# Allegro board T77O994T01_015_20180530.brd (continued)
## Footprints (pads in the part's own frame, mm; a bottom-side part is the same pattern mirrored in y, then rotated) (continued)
GMTH134R394KO472
  round 3.404 hole 3.404 unplated: (0,0)
  round 1.016 hole 0.711: 1(3.39,1.82) 2(1.738,3.245) 3(-1.835,3.159) 4(-3.357,1.821) 5(-3.357,-1.797) 6(-1.846,-3.211) 7(1.706,-3.211) 8(3.38,-1.797)
ICT
  round 0.762 smd: 1(0,0)
ICT020
  round 0.508 smd: 1(0,0)
ICT295PAS0
  round 7.493 smd: 1(0,0)
L-S4_45X4_06-2AS0
  rect 2.159x1.651 smd: 1(0,-1.908) 2(0,1.908)
L-S5_49X5_18-2
  rect 2.819x1.905 smd: 1(0,2.296) 2(0,-2.296)
L-S5_49X5_18-2A
  rect 2.819x1.905 smd: 1(0,-2.033) 2(0,2.033)
L-S6_86X6_47-2A
  rect 3.429x2.083 smd: 1(0,-2.894) 2(0,2.894)
L-S8_3X8_1-2
  rect 3.505x2.21 smd: 1(0,-3.553) 2(0,3.553)
L-U58O293T00
  rect 0.889x0.635 smd: 1(2.36,0) 2(-2.36,0)
LD-0603S0
  rect 0.813x0.762 smd: 1(0,0.686) 2(0,-0.686)
LD-0603S0-H0_55
  rect 0.813x0.762 smd: 1(0,0.686) 2(0,-0.686)
MPTH126R295
  round 7.493 hole 3.2: 1(0,0)
MSOP-8
  rect 1.524x0.356 smd: 1(2.07,-0.975) 2(2.07,-0.325) 3(2.07,0.325) 4(2.07,0.975) 5(-2.07,0.975) 6(-2.07,0.325) 7(-2.07,-0.325) 8(-2.07,-0.975)
MSOP-8A
  rect 1.524x0.356 smd: 1(2.819,-0.975) 2(2.819,-0.325) 3(2.819,0.325) 4(2.819,0.975) 5(-2.819,0.975) 6(-2.819,0.325) 7(-2.819,-0.325) 8(-2.819,-0.975)
NUT165R276-H5_7
  round 7.01 hole 4.191: 1(0,0)
O-3_2X1_5-2A
  rect 1.905x1.016 smd: 1(0,-1.25) 2(0,1.25)
O-3_2X2_5-4GS0
  rect 1.6x1.702 smd: 1(0.95,-1.25) 2(0.95,1.25) 3(-0.95,1.25) 4(-0.95,-1.25)
O-3_2X2_5-4JS0
  rect 1.6x1.372 smd: 1(-1.197,-0.978) 2(1.197,-0.978) 3(1.197,0.978) 4(-1.197,0.978)
O-S3_2X2_5-4F
  rect 1.168x1.397 smd: 1(0.8,-1.1) 2(0.8,1.1) 3(-0.8,1.1) 4(-0.8,-1.1)
PBGA-16X16-256B-H2_2
  round 0.508 smd: A1(-7.5,-7.5) A2(-7.5,-6.5) A3(-7.5,-5.5) A4(-7.5,-4.5) A5(-7.5,-3.5) A6(-7.5,-2.5) A7(-7.5,-1.5) A8(-7.5,-0.5) A9(-7.5,0.5) A10(-7.5,1.5) A11(-7.5,2.5) A12(-7.5,3.5) A13(-7.5,4.5) A14(-7.5,5.5) A15(-7.5,6.5) A16(-7.5,7.5) B1(-6.5,-7.5) B2(-6.5,-6.5) B3(-6.5,-5.5) B4(-6.5,-4.5) B5(-6.5,-3.5) B6(-6.5,-2.5) B7(-6.5,-1.5) B8(-6.5,-0.5) B9(-6.5,0.5) B10(-6.5,1.5) B11(-6.5,2.5) B12(-6.5,3.5) B13(-6.5,4.5) B14(-6.5,5.5) B15(-6.5,6.5) B16(-6.5,7.5) C1(-5.5,-7.5) C2(-5.5,-6.5) C3(-5.5,-5.5) C4(-5.5,-4.5) C5(-5.5,-3.5) C6(-5.5,-2.5) C7(-5.5,-1.5) C8(-5.5,-0.5) C9(-5.5,0.5) C10(-5.5,1.5) C11(-5.5,2.5) C12(-5.5,3.5) C13(-5.5,4.5) C14(-5.5,5.5) C15(-5.5,6.5) C16(-5.5,7.5) D1(-4.5,-7.5) D2(-4.5,-6.5) D3(-4.5,-5.5) D4(-4.5,-4.5) D5(-4.5,-3.5) D6(-4.5,-2.5) D7(-4.5,-1.5) D8(-4.5,-0.5) D9(-4.5,0.5) D10(-4.5,1.5) D11(-4.5,2.5) D12(-4.5,3.5) D13(-4.5,4.5) D14(-4.5,5.5) D15(-4.5,6.5) D16(-4.5,7.5) E1(-3.5,-7.5) E2(-3.5,-6.5) E3(-3.5,-5.5) E4(-3.5,-4.5) E5(-3.5,-3.5) E6(-3.5,-2.5) E7(-3.5,-1.5) E8(-3.5,-0.5) E9(-3.5,0.5) E10(-3.5,1.5) E11(-3.5,2.5) E12(-3.5,3.5) E13(-3.5,4.5) E14(-3.5,5.5) E15(-3.5,6.5) E16(-3.5,7.5) F1(-2.5,-7.5) F2(-2.5,-6.5) F3(-2.5,-5.5) F4(-2.5,-4.5) F5(-2.5,-3.5) F6(-2.5,-2.5) F7(-2.5,-1.5) F8(-2.5,-0.5) F9(-2.5,0.5) F10(-2.5,1.5) F11(-2.5,2.5) F12(-2.5,3.5) F13(-2.5,4.5) F14(-2.5,5.5) F15(-2.5,6.5) F16(-2.5,7.5) G1(-1.5,-7.5) G2(-1.5,-6.5) G3(-1.5,-5.5) G4(-1.5,-4.5) G5(-1.5,-3.5) G6(-1.5,-2.5) G7(-1.5,-1.5) G8(-1.5,-0.5) G9(-1.5,0.5) G10(-1.5,1.5) G11(-1.5,2.5) G12(-1.5,3.5) G13(-1.5,4.5) G14(-1.5,5.5) G15(-1.5,6.5) G16(-1.5,7.5) H1(-0.5,-7.5) H2(-0.5,-6.5) H3(-0.5,-5.5) H4(-0.5,-4.5) H5(-0.5,-3.5) H6(-0.5,-2.5) H7(-0.5,-1.5) H8(-0.5,-0.5) H9(-0.5,0.5) H10(-0.5,1.5) H11(-0.5,2.5) H12(-0.5,3.5) H13(-0.5,4.5) H14(-0.5,5.5) H15(-0.5,6.5) H16(-0.5,7.5) J1(0.5,-7.5) J2(0.5,-6.5) J3(0.5,-5.5) J4(0.5,-4.5) J5(0.5,-3.5) J6(0.5,-2.5) J7(0.5,-1.5) J8(0.5,-0.5) J9(0.5,0.5) J10(0.5,1.5) J11(0.5,2.5) J12(0.5,3.5) J13(0.5,4.5) J14(0.5,5.5) J15(0.5,6.5) J16(0.5,7.5) K1(1.5,-7.5) K2(1.5,-6.5) K3(1.5,-5.5) K4(1.5,-4.5) K5(1.5,-3.5) K6(1.5,-2.5) K7(1.5,-1.5) K8(1.5,-0.5) K9(1.5,0.5) K10(1.5,1.5) K11(1.5,2.5) K12(1.5,3.5) K13(1.5,4.5) K14(1.5,5.5) K15(1.5,6.5) K16(1.5,7.5) L1(2.5,-7.5) L2(2.5,-6.5) L3(2.5,-5.5) L4(2.5,-4.5) L5(2.5,-3.5) L6(2.5,-2.5) L7(2.5,-1.5) L8(2.5,-0.5) L9(2.5,0.5) L10(2.5,1.5) L11(2.5,2.5) L12(2.5,3.5) L13(2.5,4.5) L14(2.5,5.5) L15(2.5,6.5) L16(2.5,7.5) M1(3.5,-7.5) M2(3.5,-6.5) M3(3.5,-5.5) M4(3.5,-4.5) M5(3.5,-3.5) M6(3.5,-2.5) M7(3.5,-1.5) M8(3.5,-0.5) M9(3.5,0.5) M10(3.5,1.5) M11(3.5,2.5) M12(3.5,3.5) M13(3.5,4.5) M14(3.5,5.5) M15(3.5,6.5) M16(3.5,7.5) N1(4.5,-7.5) N2(4.5,-6.5) N3(4.5,-5.5) N4(4.5,-4.5) N5(4.5,-3.5) N6(4.5,-2.5) N7(4.5,-1.5) N8(4.5,-0.5) N9(4.5,0.5) N10(4.5,1.5) N11(4.5,2.5) N12(4.5,3.5) N13(4.5,4.5) N14(4.5,5.5) N15(4.5,6.5) N16(4.5,7.5) P1(5.5,-7.5) P2(5.5,-6.5) P3(5.5,-5.5) P4(5.5,-4.5) P5(5.5,-3.5) P6(5.5,-2.5) P7(5.5,-1.5) P8(5.5,-0.5) P9(5.5,0.5) P10(5.5,1.5) P11(5.5,2.5) P12(5.5,3.5) P13(5.5,4.5) P14(5.5,5.5) P15(5.5,6.5) P16(5.5,7.5) R1(6.5,-7.5) R2(6.5,-6.5) R3(6.5,-5.5) R4(6.5,-4.5) R5(6.5,-3.5) R6(6.5,-2.5) R7(6.5,-1.5) R8(6.5,-0.5) R9(6.5,0.5) R10(6.5,1.5) R11(6.5,2.5) R12(6.5,3.5) R13(6.5,4.5) R14(6.5,5.5) R15(6.5,6.5) R16(6.5,7.5) T1(7.5,-7.5) T2(7.5,-6.5) T3(7.5,-5.5) T4(7.5,-4.5) T5(7.5,-3.5) T6(7.5,-2.5) T7(7.5,-1.5) T8(7.5,-0.5) T9(7.5,0.5) T10(7.5,1.5) T11(7.5,2.5) T12(7.5,3.5) T13(7.5,4.5) T14(7.5,5.5) T15(7.5,6.5) T16(7.5,7.5)
R-0402H016HS40
  custom 0.114x0.114 smd: 1(0,-0.381) 2(0,0.381)
R-0402S0
  custom 0.127x0.127 smd: 1(0,-0.406) 2(0,0.406)
R-0603-TESTS1
  custom 0.191x0.191 smd: 1(0,-0.686)
  custom 0.229x0.229 smd: 2(0,0.686)
R-0603S0
  custom 0.191x0.191 smd: 1(0,-0.686) 2(0,0.686)
R-0805
  custom 0.254x0.254 smd: 1(0,-0.889) 2(0,0.889)
R-1206
  custom 0.362x0.362 smd: 1(0,-1.333) 2(0,1.333)
R-1210
  custom 0.381x0.381 smd: 1(0,-1.27) 2(0,1.27)
R-2010
  custom 0.464x0.464 smd: 1(0,-2.121) 2(0,2.121)
R-S3_1X1_6-2
  custom 0.362x0.362 smd: 1(0,-1.333) 2(0,1.333)
S-UQFN-4X4-32BSH
  custom 0.064x0.064 smd: 1(-1.4,-1.956) 8(1.4,-1.956) 9(1.956,-1.4) 16(1.956,1.4) 17(1.4,1.956) 24(-1.4,1.956) 25(-1.956,1.4) 32(-1.956,-1.4)
  rect 0.254x0.813 smd: 2(-1,-1.956) 3(-0.6,-1.956) 4(-0.2,-1.956) 5(0.2,-1.956) 6(0.6,-1.956) 7(1,-1.956) 18(1,1.956) 19(0.6,1.956) 20(0.2,1.956) 21(-0.2,1.956) 22(-0.6,1.956) 23(-1,1.956)
  rect 0.813x0.254 smd: 10(1.956,-1) 11(1.956,-0.6) 12(1.956,-0.2) 13(1.956,0.2) 14(1.956,0.6) 15(1.956,1) 26(-1.956,1) 27(-1.956,0.6) 28(-1.956,0.2) 29(-1.956,-0.2) 30(-1.956,-0.6) 31(-1.956,-1)
  rect 2.794x2.794 smd: 33(0,0)
SC-70-5A
  rect 0.914x0.356 smd: 1(1.003,-0.65) 2(1.003,0) 3(1.003,0.65) 4(-1.003,0.65) 5(-1.003,-0.65)
SO-8G
  rect 1.651x0.635 smd: 1(3.52,-1.905) 2(3.52,-0.635) 3(3.52,0.635) 4(3.52,1.905) 5(-3.52,1.905) 6(-3.52,0.635) 7(-3.52,-0.635) 8(-3.52,-1.905)
SO-8GSHS0
  rect 1.651x0.635 smd: 1(2.555,-1.905) 2(2.555,-0.635) 3(2.555,0.635) 4(2.555,1.905) 5(-2.555,1.905) 6(-2.555,0.635) 7(-2.555,-0.635) 8(-2.555,-1.905)
  rect 2.388x3.2 smd: 9(0,0)
SO-8H1_75
  rect 1.651x0.635 smd: 1(2.555,-1.905) 2(2.555,-0.635) 3(2.555,0.635) 4(2.555,1.905) 5(-2.555,1.905) 6(-2.555,0.635) 7(-2.555,-0.635) 8(-2.555,-1.905)
SOT-23-6
  rect 1.067x0.559 smd: 1(1.359,-0.95) 2(1.359,0) 3(1.359,0.95) 4(-1.359,0.95) 5(-1.359,0) 6(-1.359,-0.95)
SOT-23-8A
  rect 1.194x0.406 smd: 1(1.3,-0.975) 2(1.3,-0.325) 3(1.3,0.325) 4(1.3,0.975) 5(-1.3,0.975) 6(-1.3,0.325) 7(-1.3,-0.325) 8(-1.3,-0.975)
SOT-23BH1_11
  rect 1.067x1.016 smd: 1(0.92,-0.951) 2(0.92,0.951) 3(-0.921,0)
SOT-353-H1_1S0
  rect 0.914x0.356 smd: 1(1.003,-0.65) 2(1.003,0) 3(1.003,0.65) 4(-1.003,0.65) 5(-1.003,-0.65)
SOT-363S0
  rect 0.914x0.356 smd: 1(1.003,-0.65) 2(1.003,0) 3(1.003,0.65) 4(-1.003,0.65) 5(-1.003,0) 6(-1.003,-0.65)
SSOP-16C
  rect 1.524x0.356 smd: 1(2.819,-2.275) 2(2.819,-1.625) 3(2.819,-0.975) 4(2.819,-0.325) 5(2.819,0.325) 6(2.819,0.975) 7(2.819,1.625) 8(2.819,2.275) 9(-2.819,2.275) 10(-2.819,1.625) 11(-2.819,0.975) 12(-2.819,0.325) 13(-2.819,-0.325) 14(-2.819,-0.975) 15(-2.819,-1.625) 16(-2.819,-2.275)
SSOP-20
  rect 1.524x0.356 smd: 1(2.819,-2.925) 2(2.819,-2.275) 3(2.819,-1.625) 4(2.819,-0.975) 5(2.819,-0.325) 6(2.819,0.325) 7(2.819,0.975) 8(2.819,1.625) 9(2.819,2.275) 10(2.819,2.925) 11(-2.819,2.925) 12(-2.819,2.275) 13(-2.819,1.625) 14(-2.819,0.975) 15(-2.819,0.325) 16(-2.819,-0.325) 17(-2.819,-0.975) 18(-2.819,-1.625) 19(-2.819,-2.275) 20(-2.819,-2.925)
SSOP-24C
  rect 1.524x0.356 smd: 1(2.819,-3.575) 2(2.819,-2.925) 3(2.819,-2.275) 4(2.819,-1.625) 5(2.819,-0.975) 6(2.819,-0.325) 7(2.819,0.325) 8(2.819,0.975) 9(2.819,1.625) 10(2.819,2.275) 11(2.819,2.925) 12(2.819,3.575) 13(-2.819,3.575) 14(-2.819,2.925) 15(-2.819,2.275) 16(-2.819,1.625) 17(-2.819,0.975) 18(-2.819,0.325) 19(-2.819,-0.325) 20(-2.819,-0.975) 21(-2.819,-1.625) 22(-2.819,-2.275) 23(-2.819,-2.925) 24(-2.819,-3.575)
TLGA-3X3-12SH
  rect 0.635x0.381 smd: 1(1.467,-1.25) 2(1.467,-0.75) 3(1.467,-0.25) 4(1.467,0.25) 5(1.467,0.75) 6(1.467,1.25) 7(-1.467,1.25) 8(-1.467,0.75) 9(-1.467,0.25) 10(-1.467,-0.25) 11(-1.467,-0.75) 12(-1.467,-1.25)
  rect 2.057x2.794 smd: 13(0,0)
TQFN-2X2-8FSHS0
  rect 0.483x0.381 smd: 1(0.911,-0.75) 2(0.911,-0.25) 3(0.911,0.25) 4(0.911,0.75) 5(-0.911,0.75) 6(-0.911,0.25)
  rect 0.203x0.203 smd: 7(-0.898,-0.252) 8(-0.893,-0.748)
  rect 0.991x1.702 smd: 9(0,0)
TQFN-3X3-10FSHS1
  rect 0.813x0.381 smd: 1(1.455,-1) 2(1.455,-0.5) 3(1.455,0) 4(1.455,0.5) 5(1.455,1) 6(-1.455,1) 7(-1.455,0.5) 8(-1.455,0) 9(-1.455,-0.5) 10(-1.455,-1)
  rect 1.727x2.565 smd: 11(0,0)
TQFN-3X3-10GSH
  rect 0.813x0.381 smd: 1(1.455,-1) 2(1.455,-0.5) 3(1.455,0) 4(1.455,0.5) 5(1.455,1) 6(-1.455,1) 7(-1.455,0.5) 8(-1.455,0) 9(-1.455,-0.5) 10(-1.455,-1)
  custom 0.423x0.423 smd: 11(0,0)
TQFN-3X3-16TSHS0
  custom 0.095x0.095 smd: 1(-0.75,-1.457) 4(0.75,-1.457) 5(1.457,-0.75) 8(1.457,0.75) 9(0.75,1.457) 12(-0.75,1.457) 13(-1.457,0.75) 16(-1.457,-0.75)
  rect 0.381x0.813 smd: 2(-0.25,-1.457) 3(0.25,-1.457) 10(0.25,1.457) 11(-0.25,1.457)
  rect 0.813x0.381 smd: 6(1.457,-0.25) 7(1.457,0.25) 14(-1.457,0.25) 15(-1.457,-0.25)
  rect 1.803x1.803 smd: 17(0,0)
TQFN-5X5-32NSH
  rect 0.381x0.813 smd: 1(-1.75,-2.456) 2(-1.25,-2.456) 3(-0.75,-2.456) 4(-0.25,-2.456) 5(0.25,-2.456) 6(0.75,-2.456) 7(1.25,-2.456) 8(1.751,-2.456) 17(1.751,2.456) 18(1.25,2.456) 19(0.75,2.456) 20(0.25,2.456) 21(-0.25,2.456) 22(-0.75,2.456) 23(-1.25,2.456) 24(-1.75,2.456)
  rect 0.813x0.381 smd: 9(2.455,-1.75) 10(2.455,-1.25) 11(2.455,-0.75) 12(2.455,-0.25) 13(2.455,0.25) 14(2.455,0.75) 15(2.455,1.25) 16(2.455,1.751) 25(-2.455,1.751) 26(-2.455,1.25) 27(-2.455,0.75) 28(-2.455,0.25) 29(-2.455,-0.25) 30(-2.455,-0.75) 31(-2.455,-1.25) 32(-2.455,-1.75)
  rect 3.708x3.708 smd: 33(0,0)
TQFN-6X5-22SHS1
  rect 0.914x0.381 smd: 1(2.406,-2.501) 2(2.406,-2.001) 3(2.406,-1.5) 4(2.406,-1) 5(2.406,-0.5) 8(-2.406,-0.5) 9(-2.406,-1) 10(-2.406,-1.5) 11(-2.406,-2.001) 12(-2.406,-2.501)
  rect 0.305x0.305 smd: 6(2.406,1) 7(-2.406,1)
  custom 0.85x0.85 smd: 13(0,0)
TSSOP-8S2
  rect 1.092x0.305 smd: 1(1.511,-0.75) 2(1.511,-0.25) 3(1.511,0.25) 4(1.511,0.75) 5(-1.511,0.75) 6(-1.511,0.25) 7(-1.511,-0.25) 8(-1.511,-0.75)
ULGA-1_8X1_2-8
  rect 0.864x0.297 smd: 1(0.483,-0.6) 2(0.483,-0.2) 3(0.483,0.2) 4(0.483,0.6) 5(-0.483,0.6) 6(-0.483,0.2) 7(-0.483,-0.2) 8(-0.483,-0.6)
UM-6BH1_1
  rect 0.914x0.356 smd: 1(1.003,-0.65) 2(1.003,0) 3(1.003,0.65) 4(-1.003,0.65) 5(-1.003,0) 6(-1.003,-0.65)
unnamed
  round 1.016 smd: (0,0)

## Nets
GND: BAT1.P2(CATHODE) C17.2 C18.2 C19.1 C20.1 C21.1 C22.2 C23.2 C24.1 C25.1 C26.2 C27.2 C28.2 C29.2 C30.2 C31.2 C32.2 C33.2 C34.2 C35.2 C36.2 C37.2 C38.2 C39.2 C40.2 C41.2 C42.2 C43.2 C44.2 C45.2 C46.2 C47.2 C48.2 C49.2 C50.2 C51.2 C52.2 C53.2 C54.2 C55.2 C56.2 C57.2 C58.2 C59.2 C60.2 C61.2 C62.2 C63.2 C64.2 C65.2 C66.2 C67.2 C68.2 C69.2 C70.2 C71.2 C72.2 C73.2 C74.2 C75.2 C76.2 C77.2 C78.2 C79.2 C80.2 C81.2 C82.2 C83.2 C84.2 C85.2 C86.2 C87.2 C88.2 C89.2 C90.2 C91.2 C92.2 C93.2 C94.2 C95.2 C96.2 C97.2 C98.2 C99.2 C100.2 C101.2 C102.2 C103.2 C104.2 C107.2 C108.2 C114.2 C116.2 C117.2 C118.2 C119.2 C120.2 C121.2 C122.2 C123.2 C124.2 C125.2 C126.2 C127.2 C128.2 C129.2 C130.2 C131.2 C132.2 C133.2 C134.2 C135.2 C136.2 C137.2 C138.2 C139.2 C140.2 C141.2 C144.2 C145.2 C146.2 C147.2 C148.2 C151.2 C152.2 C153.2 C154.2 C155.2 C156.2 C157.2 C158.2 C159.2 C160.2 C161.2 C162.2 C163.2 C164.2 C165.2 C166.2 C167.2 C168.2 C169.2 C170.2 C171.2 C172.2 C173.2 C174.2 C175.2 C176.2 C177.2 C178.2 C179.2 C180.2 C181.2 C182.2 C183.2 C185.2 C186.2 C187.2 C188.2 C189.2 C190.2 C191.2 C192.2 C193.2 C198.2 C199.2 C200.2 C205.2 C206.2 C207.2 C208.2 C209.2 C210.2 C3812.2 C3813.2 CN1.1(VSS_0) CN1.2(VSS_21) CN1.5(VSS_1) CN1.6(VSS_22) CN1.9(VSS_2) CN1.10(VSS_23) CN1.12(DM0_L_DBI0_L) CN1.14(VSS_24) CN1.15(VSS_3) CN1.18(VSS_25) CN1.19(VSS_4) CN1.22(VSS_26) CN1.23(VSS_5) CN1.26(VSS_27) CN1.27(VSS_6) CN1.30(VSS_28) CN1.31(VSS_7) CN1.33(DM1_L_DBI1_L) CN1.35(VSS_8) CN1.36(VSS_29) CN1.39(VSS_9) CN1.40(VSS_30) CN1.43(VSS_10) CN1.44(VSS_31) CN1.47(VSS_11) CN1.48(VSS_32) CN1.51(VSS_12) CN1.52(VSS_33) CN1.54(DM2_L_DBI2_L) CN1.56(VSS_34) CN1.57(VSS_13) CN1.60(VSS_35) CN1.61(VSS_14) CN1.64(VSS_36) CN1.65(VSS_15) CN1.68(VSS_37) CN1.69(VSS_16) CN1.72(VSS_38) CN1.73(VSS_17) CN1.75(DM3_L_DBI3_L) CN1.77(VSS_18) CN1.78(VSS_39) CN1.81(VSS_19) CN1.82(VSS_40) CN1.85(VSS_20) CN1.86(VSS_41) CN1.89(VSS_42) CN1.90(VSS_49) CN1.93(VSS_43) CN1.94(VSS_50) CN1.96(DBI8_L) CN1.98(VSS_51) CN1.99(VSS_44) CN1.102(VSS_52) CN1.103(VSS_45) CN1.106(VSS_53) CN1.107(VSS_46) CN1.167(VSS_47) CN1.168(VSS_54) CN1.171(VSS_48) CN1.172(VSS_55) CN1.175(VSS_56) CN1.176(VSS_75) CN1.178(DM4_L_DBI4_L) CN1.180(VSS_76) CN1.181(VSS_57) CN1.184(VSS_77) CN1.185(VSS_58) CN1.188(VSS_78) CN1.189(VSS_59) CN1.192(VSS_79) CN1.193(VSS_60) CN1.196(VSS_80) CN1.197(VSS_61) CN1.199(DM5_L_DBI5_L) CN1.201(VSS_62) CN1.202(VSS_81) CN1.205(VSS_63) CN1.206(VSS_82) CN1.209(VSS_64) CN1.210(VSS_83) CN1.213(VSS_65) CN1.214(VSS_84) CN1.217(VSS_66) CN1.218(VSS_85) CN1.220(DM6_L_DBI6_L) CN1.222(VSS_86) CN1.223(VSS_67) CN1.226(VSS_87) CN1.227(VSS_68) CN1.230(VSS_88) CN1.231(VSS_69) CN1.234(VSS_89) CN1.235(VSS_70) CN1.238(VSS_90) CN1.239(VSS_71) CN1.241(DM7_L_DBI7_L) CN1.243(VSS_72) CN1.244(VSS_91) CN1.247(VSS_73) CN1.248(VSS_92) CN1.251(VSS_74) CN1.252(VSS_93) CN1.S1 CN1.S2 CN2.1(VSS_0) CN2.2(VSS_21) CN2.5(VSS_1) CN2.6(VSS_22) CN2.9(VSS_2) CN2.10(VSS_23) CN2.12(DM0_L_DBI0_L) CN2.14(VSS_24) CN2.15(VSS_3) CN2.18(VSS_25) CN2.19(VSS_4) CN2.22(VSS_26) CN2.23(VSS_5) CN2.26(VSS_27) CN2.27(VSS_6) CN2.30(VSS_28) CN2.31(VSS_7) CN2.33(DM1_L_DBI1_L) CN2.35(VSS_8) CN2.36(VSS_29) CN2.39(VSS_9) CN2.40(VSS_30) CN2.43(VSS_10) CN2.44(VSS_31) CN2.47(VSS_11) CN2.48(VSS_32) CN2.51(VSS_12) CN2.52(VSS_33) CN2.54(DM2_L_DBI2_L) CN2.56(VSS_34) CN2.57(VSS_13) CN2.60(VSS_35) CN2.61(VSS_14) CN2.64(VSS_36) CN2.65(VSS_15) CN2.68(VSS_37) CN2.69(VSS_16) CN2.72(VSS_38) CN2.73(VSS_17) CN2.75(DM3_L_DBI3_L) CN2.77(VSS_18) CN2.78(VSS_39) CN2.81(VSS_19) CN2.82(VSS_40) CN2.85(VSS_20) CN2.86(VSS_41) CN2.89(VSS_42) CN2.90(VSS_49) CN2.93(VSS_43) CN2.94(VSS_50) CN2.96(DBI8_L) CN2.98(VSS_51) CN2.99(VSS_44) CN2.102(VSS_52) CN2.103(VSS_45) CN2.106(VSS_53) CN2.107(VSS_46) CN2.167(VSS_47) CN2.168(VSS_54) CN2.171(VSS_48) CN2.172(VSS_55) CN2.175(VSS_56) CN2.176(VSS_75) CN2.178(DM4_L_DBI4_L) CN2.180(VSS_76) CN2.181(VSS_57) CN2.184(VSS_77) CN2.185(VSS_58) CN2.188(VSS_78) CN2.189(VSS_59) CN2.192(VSS_79) CN2.193(VSS_60) CN2.196(VSS_80) CN2.197(VSS_61) CN2.199(DM5_L_DBI5_L) CN2.201(VSS_62) CN2.202(VSS_81) CN2.205(VSS_63) CN2.206(VSS_82) CN2.209(VSS_64) CN2.210(VSS_83) CN2.213(VSS_65) CN2.214(VSS_84) CN2.217(VSS_66) CN2.218(VSS_85) CN2.220(DM6_L_DBI6_L) CN2.222(VSS_86) CN2.223(VSS_67) CN2.226(VSS_87) CN2.227(VSS_68) CN2.230(VSS_88) CN2.231(VSS_69) CN2.234(VSS_89) CN2.235(VSS_70) CN2.238(VSS_90) CN2.239(VSS_71) CN2.241(DM7_L_DBI7_L) CN2.243(VSS_72) CN2.244(VSS_91) CN2.247(VSS_73) CN2.248(VSS_92) CN2.251(VSS_74) CN2.252(VSS_93) CN2.S1 CN2.S2 J1.2 J2.4 J6.2 J8.2 J8.10 J9.3(GND_3) J9.9(GND_9) J9.15(GND_15) J9.27(GND_27) J9.33(GND_33) J9.39(GND_39) J9.45(GND_45) J9.51(GND_51) J9.57(GND_57) J9.71(GND_71) J9.73(GND_73) J9.S1 J9.S2 J10.A4(GND_1) J10.A12(GND_2) J10.A15(GND_3) J10.A18(GND_4) J10.A20(GND_5) J10.A23(GND_6) J10.A24(GND_7) J10.A27(GND_8) J10.A28(GND_9) J10.A31(GND_10) J10.A34(GND_11) J10.A37(GND_12) J10.A38(GND_13) J10.A41(GND_14) J10.A42(GND_15) J10.A45(GND_16) J10.A46(GND_17) J10.A49(GND_18) J10.A51(GND_19) J10.A54(GND_20) J10.A55(GND_21) J10.A58(GND_22) J10.A59(GND_23) J10.A62(GND_24) J10.A63(GND_25) J10.A66(GND_26) J10.A67(GND_27) J10.A70(GND_28) J10.A71(GND_29) J10.A74(GND_30) J10.A75(GND_31) J10.A78(GND_32) J10.A79(GND_33) J10.A82(GND_34) J10.B4(GND_35) J10.B7(GND_36) J10.B13(GND_37) J10.B16(GND_38) J10.B18(GND_39) J10.B21(GND_40) J10.B22(GND_41) J10.B25(GND_42) J10.B26(GND_43) J10.B29(GND_44) J10.B32(GND_45) J10.B35(GND_46) J10.B36(GND_47) J10.B39(GND_48) J10.B40(GND_49) J10.B43(GND_50) J10.B44(GND_51) J10.B47(GND_52) J10.B49(GND_53) J10.B52(GND_54) J10.B53(GND_55) J10.B56(GND_56) J10.B57(GND_57) J10.B60(GND_58) J10.B61(GND_59) J10.B64(GND_60) J10.B65(GND_61) J10.B68(GND_62) J10.B69(GND_63) J10.B72(GND_64) J10.B73(GND_65) J10.B76(GND_66) J10.B77(GND_67) J10.B80(GND_68) J11.1 J11.2 J12.1 J12.2 J12.7 J12.8 J12.13 J12.14 J12.19 J12.20 J12.25 J12.26 J12.31 J12.32 J12.37 J12.38 J12.49 J12.50 J12.59 M1.1(GND1) M1.2(GND2) M1.3(GND3) M1.4(GND4) M1.5(GND5) M1.6(GND6) M1.7(GND7) M1.8(GND8) M2.1(GND1) M2.2(GND2) M2.3(GND3) M2.4(GND4) M2.5(GND5) M2.6(GND6) M2.7(GND7) M2.8(GND8) M3.1(GND1) M3.2(GND2) M3.3(GND3) M3.4(GND4) M3.5(GND5) M3.6(GND6) M3.7(GND7) M3.8(GND8) M4.1(GND1) M4.2(GND2) M4.3(GND3) M4.4(GND4) M4.5(GND5) M4.6(GND6) M4.7(GND7) M4.8(GND8) MHS1.1 MHS2.1 MHS3.1 MHS4.1 PC1.2 PC3.2 PC6.2 PC7.2 PC8.2 PC9.2 PC10.2 PC11.2 PC12.2 PC13.2 PC15.2 PC16.2 PC17.2 PC20.2 PC22.2 PC23.2 PC24.2 PC25.2 PC26.2 PC27.2 PC28.2 PC29.2 PC30.2 PC31.2 PC32.2 PC33.2 PC34.2 PC35.2 PC36.2 PC37.2 PC38.2 PC39.2 PC40.2 PC41.2 PC44.2 PC45.2 PC46.2 PC47.2 PC48.2 PC52.2 PC67.2 PC68.2 PC69.2 PC70.2 PC71.2 PC72.2 PC75.2 PC77.2 PC78.2 PC79.2 PC80.2 PC81.2 PC82.2 PC83.2 PC84.2 PC111.2 PC112.2 PC114.2 PC115.2 PC139.2 PC140.2 PC142.2 PC144.2 PC146.2 PC147.2 PC148.2 PC151.2 PC152.2(C) PC162.2 PC163.2 PC166.2 PC170.2 PC171.2 PC172.2 PC173.2(C) PC174.2 PC175.2 PC176.2 PC179.2(C) PC180.2 PC182.2 PC183.2 PC184.2 PC185.2(C) PC194.2 PC195.2 PC196.2 PC199.2 PC200.2 PC201.2 PC202.2 PC203.2 PC204.2 PC205.2 PC206.2 PC208.2 PC209.2 PC211.2 PC212.2 PC213.2 PC216.2 PC217.2 PC218.2 PC219.2 PC220.2 PC222.2 PC223.2 PC224.2 PC225.2 PC226.2 PC227.2 PC228.2 PC229.2 PC230.2 PC231.2 PC232.2(C) PC237.2(C) PC242.2(C) PC243.2 PC244.2 PC246.2 PC247.2 PC248.2 PC249.2 PC250.2 PC252.2 PC255.2 PC256.2(C) PC257.2 PC258.2 PC259.2 PC262.2 PC263.2 PC264.2 PC265.2 PC266.2 PC267.2 PC270.2 PC271.2 PC272.2 PC273.2 PC274.2 PC275.2 PC284.2(C) PC292.2(C) PC293.2(C) PC295.2 PC296.2 PC297.2 PC298.2 PC299.2 PC300.2 PC301.2 PC302.2 PC303.2 PC304.2 PC305.2 PC306.2 PC307.2 PC309.2 PC316.2 PC318.2 PC322.2 PC323.2(C) PC324.2(C) PC325.2 PC326.2 PC327.2 PC330.2 PC331.2 PC336.2 PC340.2 PC349.2 PJ20.2 PJ21.2 PJ22.2 PR1.2 PR2.2 PR12.2 PR14.2 PR17.2 PR19.2 PR20.2 PR24.2 PR25.2 PR32.2 PR34.2 PR37.2 PR116.2 PR123.2 PR136.2 PR160.2 PR187.2 PR192.1 PR192.2 PR207.2 PR215.1 PR217.2 PR222.2 PR223.2 PR226.2 PR228.2 PR231.2 PR233.2 PR235.2 PR237.2 PR239.2 PR246.2 PR259.2 PR260.2 PR265.2 PR278.2 PR304.2 PU1.1(GND) PU2.5(GND) PU2.9(PAD) PU5.6(GND) PU5.11(E-PAD) PU6.6(GND) PU6.11(E-PAD) PU11.4(PGND) PU11.8(GND) PU11.11(E-PAD) PU14.3(GND1) PU14.4(GND2) PU14.5(AGND) PU14.17(POWER PAD) PU18.13(PGND) PU19.13(PGND) PU20.1(GND) PU22.13(PGND) PU24.4(GND) PU25.4(GND) PU26.13(PGND) Q1.1(S1) Q1.4(S2) Q2.2(E) Q3.2(E) Q4.1(S1) Q4.4(S2) Q5.1(S1) Q5.4(S2) Q6.2(E) R2.1 R3.1 R16.1 R17.2 R32.2 R37.1 R38.1 R84.1 R87.1 R90.1 R93.1 R95.1 R96.2 R97.1 R100.2 R123.1 R124.1 R131.1 R132.1 R135.1 R137.1 R138.1 R140.1 R141.1 R142.1 R143.1 R144.1 R145.1 R147.1 R149.2 R166.2 R167.2 R168.2 R169.1 R170.1 R171.1 R172.1 R173.1 R176.1 R178.2 R179.2 R185.2 R191.2 R203.2 R212.2 R222.2 R224.2 R226.2 R232.2 R233.2 R234.2 R238.2 R239.2 R244.2 R245.2 R246.2 R247.2 R253.1 R254.2 R255.2 R256.2 R257.2 R263.2 R264.2 R265.2 R266.2 R267.2 R274.2 R275.2 R276.2 R277.2 R282.2 R283.2 R284.2 R285.2 R286.2 R292.2 R293.2 R294.2 R295.2 R300.2 R301.2 R302.2 R303.2 R319.2 R320.2 R321.2 R336.2 R337.2 R350.1 R352.1 R362.2 R369.2 R387.2 R423.2 R425.2 R427.2 R429.2 R431.2 R433.2 R435.2 R446.2 R448.1 R449.2 R460.1 U1.A3(VSS1) U1.A5(VSS3) U1.A6(VSS4) U1.A20(VSS0) U1.A77(VSS6) U1.AA12(VSS2) U1.AA14(VSS533) U1.AA16(VSS534) U1.AA19(VSS530) U1.AA21(VSS18) U1.AA23(VSS7) U1.AA25(VSS8) U1.AA56(VSS11) U1.AA60(VSS12) U1.AA62(VSS13) U1.AA69(VSS14) U1.AB5(VSS15) U1.AB74(VSS16) U1.AC2(VSS21) U1.AC12(VSS17) U1.AC16(VSS19) U1.AC18(VSS20) U1.AC27(VSS22) U1.AC58(VSS24) U1.AD5(VSS26) U1.AE7(VSS32) U1.AE11(VSS27) U1.AE14(VSS23) U1.AE19(VSS28) U1.AE23(VSS29) U1.AE64(VSS30) U1.AE67(VSS31) U1.AE71(VSS33) U1.AF5(VSS34) U1.AF9(VSS38) U1.AF74(VSS35) U1.AF76(VSS36) U1.AF78(VSS37) U1.AG12(VSS41) U1.AG16(VSS52) U1.AG21(VSS542) U1.AG62(VSS39) U1.AH3(VSS48) U1.AH5(VSS50) U1.AH12(VSS40) U1.AH16(VSS42) U1.AH18(VSS43) U1.AH19(VSS44) U1.AH25(VSS45) U1.AH27(VSS46) U1.AH28(VSS47) U1.AH30(VSS49) U1.AH53(VSS51) U1.AH56(VSS53) U1.AH66(VSS54) U1.AH69(VSS55) U1.AH74(VSS56) U1.AK12(VSS543) U1.AK16(VSS57) U1.AK19(VSS58) U1.AK60(VSS61) U1.AK75(VSS62) U1.AK77(VSS63) U1.AL7(VSS67) U1.AL11(VSS64) U1.AL64(VSS65) U1.AL67(VSS66) U1.AL71(VSS68) U1.AM9(VSS73) U1.AM19(VSS69) U1.AM21(VSS70) U1.AM28(VSS71) U1.AM30(VSS72) U1.AN5(VSS74) U1.AN74(VSS75) U1.AN76(VSS76) U1.AP14(VSS77) U1.AP19(VSS78) U1.AP23(VSS79) U1.AP53(VSS59) U1.AR1(VSS82) U1.AR3(VSS86) U1.AR5(VSS87) U1.AR12(VSS83) U1.AR19(VSS84) U1.AR25(VSS85) U1.AR53(VSS60) U1.AR55(VSS88) U1.AR56(VSS80) U1.AR60(VSS89) U1.AU1(VSS92) U1.AU3(VSS97) U1.AU5(VSS99) U1.AU19(VSS93) U1.AU23(VSS94) U1.AU25(VSS95) U1.AU28(VSS96) U1.AU30(VSS98) U1.AU53(VSS123) U1.AU55(VSS100) U1.AU56(VSS101) U1.AU58(VSS102) U1.AU62(VSS103) U1.AU66(VSS104) U1.AU69(VSS105) U1.AU72(VSS106) U1.AU74(VSS107) U1.AU76(VSS91) U1.AU78(VSS90) U1.AV2(VSS190) U1.AV64(VSS108) U1.AV67(VSS109) U1.AV71(VSS110) U1.AV75(VSS111) U1.AV77(VSS112) U1.AW5(VSS113) U1.AW9(VSS114) U1.B2(VSS115) U1.B3(VSS531) U1.B48(VSS191) U1.B61(VSS416) U1.B74(VSS10) U1.B76(VSS436) U1.B77(VSS117) U1.B78(VSS118) U1.BA3(VSS122) U1.BA12(VSS119) U1.BA16(VSS120) U1.BA28(VSS121) U1.BA56(VSS124) U1.BB2(VSS203) U1.BB19(VSS125) U1.BB33(VSS255) U1.BB35(VSS126) U1.BD1(VSS127) U1.BD5(VSS130) U1.BD14(VSS128) U1.BD33(VSS129) U1.BE9(VSS138) U1.BE28(VSS131) U1.BE35(VSS132) U1.BE66(VSS133) U1.BE69(VSS134) U1.BE72(VSS135) U1.BE75(VSS136) U1.BE77(VSS137) U1.BF5(VSS141) U1.BF26(VSS139) U1.BF30(VSS140) U1.BF56(VSS142) U1.BF64(VSS143) U1.BF67(VSS144) U1.BF71(VSS145) U1.BF74(VSS146) U1.BF76(VSS147) U1.BF78(VSS148) U1.BG24(VSS149) U1.BG35(VSS150) U1.BG62(VSS151) U1.BG69(VSS152) U1.BH3(VSS156) U1.BH5(VSS158) U1.BH11(VSS153) U1.BH14(VSS154) U1.BH18(VSS155) U1.BH30(VSS157) U1.BH60(VSS159) U1.BH64(VSS160) U1.BH74(VSS161) U1.BJ24(VSS162) U1.BJ35(VSS163) U1.BJ58(VSS164) U1.BJ69(VSS165) U1.BK1(VSS166) U1.BK5(VSS168) U1.BK37(VSS167) U1.BK74(VSS169) U1.BL30(VSS170) U1.BL56(VSS171) U1.BL64(VSS172) U1.BM9(VSS180) U1.BM13(VSS173) U1.BM16(VSS174) U1.BM20(VSS175) U1.BM24(VSS176) U1.BM35(VSS177) U1.BM58(VSS432) U1.BM69(VSS178) U1.BM74(VSS179) U1.BN30(VSS181) U1.BN37(VSS182) U1.BN56(VSS435) U1.BN60(VSS183) U1.BN64(VSS184) U1.BN75(VSS185) U1.BN77(VSS186) U1.BP3(VSS188) U1.BP24(VSS187) U1.BP35(VSS189) U1.BP62(VSS192) U1.BP69(VSS193) U1.BP74(VSS194) U1.BR11(VSS195) U1.BR14(VSS196) U1.BR18(VSS197) U1.BR22(VSS198) U1.BR30(VSS199) U1.BR64(VSS200) U1.BT24(VSS201) U1.BT35(VSS202) U1.BT56(VSS204) U1.BT58(VSS479) U1.BT69(VSS205) U1.BT74(VSS206) U1.BU2(VSS207) U1.BU4(VSS210) U1.BU30(VSS208) U1.BU37(VSS209) U1.BU64(VSS211) U1.BV9(VSS218) U1.BV13(VSS212) U1.BV24(VSS213) U1.BV35(VSS214) U1.BV56(VSS520) U1.BV58(VSS215) U1.BV62(VSS216) U1.BV69(VSS217) U1.BW5(VSS229) U1.BW7(VSS236) U1.BW11(VSS219) U1.BW14(VSS220) U1.BW30(VSS221) U1.BW39(VSS222) U1.BW40(VSS223) U1.BW42(VSS224) U1.BW43(VSS225) U1.BW45(VSS226) U1.BW47(VSS227) U1.BW49(VSS228) U1.BW50(VSS230) U1.BW52(VSS231) U1.BW54(VSS232) U1.BW55(VSS233) U1.BW60(VSS234) U1.BW64(VSS235) U1.BW74(VSS237) U1.BY16(VSS238) U1.BY20(VSS239) U1.BY24(VSS240) U1.BY28(VSS241) U1.BY35(VSS242) U1.BY39(VSS243) U1.BY43(VSS244) U1.BY54(VSS245) U1.BY58(VSS246) U1.BY62(VSS247) U1.BY66(VSS248) U1.BY69(VSS249) U1.BY72(VSS250) U1.C1(VSS251) U1.C2(VSS252) U1.C20(VSS253) U1.C77(VSS256) U1.C78(VSS257) U1.CA5(VSS267) U1.CA11(VSS258) U1.CA18(VSS259) U1.CA22(VSS260) U1.CA26(VSS261) U1.CA30(VSS262) U1.CA41(VSS263) U1.CA45(VSS264) U1.CA46(VSS265) U1.CA49(VSS266) U1.CA51(VSS268) U1.CA52(VSS269) U1.CA56(VSS270) U1.CA60(VSS271) U1.CA64(VSS272) U1.CA67(VSS273) U1.CA71(VSS274) U1.CA74(VSS275) U1.CA76(VSS276) U1.CA78(VSS277) U1.CB16(VSS278) U1.CB32(VSS279) U1.CB35(VSS280) U1.CB47(VSS281) U1.CB51(VSS282) U1.CB54(VSS283) U1.CB58(VSS284) U1.CB62(VSS285) U1.CC5(VSS292) U1.CC11(VSS286) U1.CC30(VSS287) U1.CC33(VSS288) U1.CC37(VSS289) U1.CC41(VSS290) U1.CC45(VSS291) U1.CC74(VSS293) U1.CD16(VSS294) U1.CD43(VSS295) U1.CD47(VSS296) U1.CD62(VSS297) U1.CE1(VSS298) U1.CE3(VSS299) U1.CE5(VSS300) U1.CE74(VSS301) U1.CF11(VSS302) U1.CF30(VSS303) U1.CG5(VSS308) U1.CG16(VSS304) U1.CG20(VSS305) U1.CG24(VSS306) U1.CG28(VSS307) U1.CG62(VSS309) U1.CG66(VSS310) U1.CG69(VSS311) U1.CG72(VSS312) U1.CG74(VSS313) U1.CH11(VSS314) U1.CH18(VSS315) U1.CH22(VSS316) U1.CH26(VSS317) U1.CH30(VSS318) U1.CH64(VSS319) U1.CH67(VSS320) U1.CH71(VSS321) U1.CH75(VSS322) U1.CH77(VSS323) U1.CJ5(VSS325) U1.CJ16(VSS324) U1.CJ62(VSS326) U1.CJ74(VSS327) U1.CK11(VSS328) U1.CK30(VSS329) U1.CL5(VSS331) U1.CL16(VSS330) U1.CL62(VSS332) U1.CL74(VSS333) U1.CM1(VSS334) U1.CM11(VSS335) U1.CM30(VSS336) U1.CN5(VSS337) U1.CN74(VSS338) U1.CP1(VSS339) U1.CP2(VSS344) U1.CP7(VSS357) U1.CP9(VSS362) U1.CP12(VSS340) U1.CP14(VSS341) U1.CP16(VSS342) U1.CP18(VSS343) U1.CP20(VSS345) U1.CP23(VSS346) U1.CP25(VSS347) U1.CP27(VSS348) U1.CP29(VSS349) U1.CP31(VSS350) U1.CP34(VSS351) U1.CP36(VSS352) U1.CP64(VSS354) U1.CP66(VSS355) U1.CP70(VSS358) U1.CP72(VSS359) U1.CP77(VSS360) U1.CP78(VSS361) U1.CR1(VSS363) U1.CR2(VSS364) U1.CR3(VSS366) U1.CR5(VSS368) U1.CR21(VSS365) U1.CR37(VSS367) U1.CR77(VSS369) U1.CR78(VSS370) U1.CT14(VSS371) U1.CT29(VSS372) U1.CT70(VSS373) U1.CU1(VSS374) U1.CU2(VSS375) U1.CU3(VSS377) U1.CU21(VSS376) U1.CU37(VSS378) U1.CU77(VSS379) U1.CU78(VSS380) U1.CV2(VSS382) U1.CV3(VSS384) U1.CV5(VSS385) U1.CV6(VSS386) U1.CV14(VSS381) U1.CV29(VSS383) U1.CV70(VSS387) U1.CV73(VSS388) U1.CV74(VSS389) U1.CV76(VSS390) U1.CV77(VSS391) U1.D5(VSS532) U1.D48(VSS521) U1.D61(VSS392) U1.E1(VSS393) U1.E2(VSS398) U1.E5(VSS413) U1.E7(VSS423) U1.E9(VSS429) U1.E12(VSS394) U1.E14(VSS395) U1.E16(VSS396) U1.E18(VSS397) U1.E20(VSS399) U1.E23(VSS400) U1.E25(VSS401) U1.E27(VSS402) U1.E29(VSS403) U1.E31(VSS404) U1.E34(VSS405) U1.E36(VSS406) U1.E38(VSS407) U1.E40(VSS408) U1.E42(VSS409) U1.E44(VSS410) U1.E47(VSS411) U1.E49(VSS412) U1.E51(VSS414) U1.E53(VSS415) U1.E58(VSS417) U1.E60(VSS418) U1.E62(VSS419) U1.E64(VSS420) U1.E66(VSS421) U1.E68(VSS422) U1.E70(VSS424) U1.E74(VSS426) U1.E77(VSS427) U1.E78(VSS428) U1.F1(VSS430) U1.F3(VSS9) U1.F72(VSS116) U1.F78(VSS25) U1.H56(VSS425) U1.H60(VSS433) U1.H67(VSS434) U1.J3(VSS529) U1.J72(VSS437) U1.J74(VSS438) U1.K4(VSS535) U1.K56(VSS431) U1.K60(VSS439) U1.K67(VSS440) U1.L1(VSS536) U1.L3(VSS254) U1.L5(VSS451) U1.L9(VSS457) U1.L13(VSS441) U1.L16(VSS442) U1.L20(VSS443) U1.L24(VSS444) U1.L28(VSS445) U1.L32(VSS446) U1.L35(VSS447) U1.L39(VSS448) U1.L43(VSS449) U1.L47(VSS450) U1.L51(VSS452) U1.L58(VSS453) U1.L62(VSS454) U1.L66(VSS455) U1.L69(VSS5) U1.L74(VSS456) U1.M7(VSS473) U1.M11(VSS458) U1.M14(VSS459) U1.M18(VSS460) U1.M22(VSS461) U1.M26(VSS462) U1.M30(VSS463) U1.M33(VSS464) U1.M37(VSS465) U1.M41(VSS466) U1.M45(VSS467) U1.M49(VSS468) U1.M52(VSS469) U1.M56(VSS470) U1.M60(VSS471) U1.M64(VSS472) U1.M71(VSS474) U1.N5(VSS475) U1.N66(VSS476) U1.N74(VSS477) U1.N76(VSS478) U1.P52(VSS480) U1.P60(VSS481) U1.R35(VSS482) U1.R37(VSS483) U1.R40(VSS484) U1.R42(VSS485) U1.R46(VSS81) U1.R54(VSS486) U1.R66(VSS487) U1.R69(VSS488) U1.T5(VSS492) U1.T11(VSS489) U1.T33(VSS490) U1.T39(VSS491) U1.T60(VSS493) U1.T74(VSS494) U1.U9(VSS502) U1.U13(VSS495) U1.U16(VSS496) U1.U20(VSS497) U1.U24(VSS498) U1.U28(VSS499) U1.U32(VSS500) U1.U66(VSS501) U1.V1(VSS537) U1.V3(VSS538) U1.V5(VSS512) U1.V7(VSS517) U1.V14(VSS503) U1.V18(VSS504) U1.V22(VSS505) U1.V26(VSS506) U1.V30(VSS507) U1.V35(VSS508) U1.V42(VSS509) U1.V44(VSS510) U1.V46(VSS511) U1.V55(VSS513) U1.V60(VSS514) U1.V62(VSS515) U1.V64(VSS516) U1.V71(VSS518) U1.W13(VSS539) U1.W16(VSS540) U1.W24(VSS541) U1.Y5(VSS525) U1.Y39(VSS522) U1.Y40(VSS523) U1.Y42(VSS524) U1.Y55(VSS526) U1.Y74(VSS527) U1.Y76(VSS528) U2.2(GND) U3.4(GND) U4.2(1DIR) U4.3(2DIR) U4.8(GND1) U4.9(GND2) U4.14(\2\O\E\) U4.15(\1\O\E\) U5.4(GND) U7.4(GND) U8.2(1DIR) U8.8(GND1) U8.9(GND2) U8.14(\2\O\E\) U8.15(\1\O\E\) U9.4(GND) U10.2(1DIR) U10.3(2DIR) U10.8(GND1) U10.9(GND2) U10.14(\2\O\E\) U10.15(\1\O\E\) U11.2(1DIR) U11.3(2DIR) U11.8(GND1) U11.9(GND2) U11.14(\2\O\E\) U11.15(\1\O\E\) U12.3(GND) U13.2(1DIR) U13.3(2DIR) U13.8(GND1) U13.9(GND2) U13.14(\2\O\E\) U13.15(\1\O\E\) U14.2(1DIR) U14.3(2DIR) U14.8(GND1) U14.9(GND2) U14.14(\2\O\E\) U14.15(\1\O\E\) U15.8(GND1) U15.9(GND2) U15.14(\2\O\E\) U15.15(\1\O\E\) U16.2(GND) U17.3(GND) U18.3(GND) U19.3(GND) U20.10(GND) U21.2(GND) U22.2(GND) U23.4(GND) U24.4(GND) U25.2(GND_1) U25.9(GND_2) U25.16(NCI/GND) U25.23(GND_3) U25.32(GND_4) U25.33(EEPAD) U26.4(GND) U27.4(GND) U28.3(GND) U29.3(GND) U30.12(VSS) U31.A1(GNDIO_1) U31.A16(GNDIO_2) U31.B2(GNDIO_3) U31.B15(GNDIO_4) U31.G5(GND_40) U31.G7(GNDIO_5) U31.G8(GNDIO_6) U31.G9(GNDIO_7) U31.G10(GNDIO_8) U31.H7(GNDINT_1) U31.H9(GNDINT_2) U31.J8(GNDINT_3) U31.J10(GNDINT_4) U31.K7(GNDIO_9) U31.K8(GNDIO_10) U31.K9(GNDIO_11) U31.K10(GNDIO_12) U31.R2(GNDIO_13) U31.R15(GNDIO_14) U31.T1(GNDIO_15) U31.T16(GNDIO_16) U32.2(GND) U33.3(GND) U34.2(GND) U35.4(GND) U36.2(GND) Y1.2 Y1.4 Y3.2 Y3.4 Y4.2(GND)
SGND_VCORE: PC187.2 PC188.2 PC189.2 PC192.2 PC193.2 PJ20.1 PR133.2 PR140.2 PR141.2 PR147.2 PR148.2 PR149.2 PR156.2 PR202.2 PU17.22(CSN3) PU17.29(GND) PU17.33(GND2)
SGND_VP1P2_DDR4_VDD: PC233.2 PC234.2 PC235.2 PC239.2 PC240.2 PJ21.1 PR157.2 PR158.2 PR176.2 PR177.2 PR178.2 PR189.2 PR200.2 PU21.19(CSN2) PU21.22(N/C2) PU21.29(GND) PU21.33(T_PAD)
SGND_VP1P05: PC329.2 PC332.2 PC339.2 PC347.2 PC348.2 PJ22.1 PR269.2 PR274.2 PR275.2 PR284.2 PR285.2 PR296.2 PR300.2 PU27.19(CSN2) PU27.22(N/C2) PU27.29(GND) PU27.33(T_PAD)
VCC_CORE_VIN_SHAPE: PC170.1 PC171.1 PC172.1 PC182.1 PC183.1 PC184.1 PC273.1 PC274.1 PL11.2 PU18.7(VIN) PU19.7(VIN)
VCC_SENSE: PR137.2 PR154.1 U1.AT77(VCCIN_SENSE)
VCCINT_CPLD: R364.1 R365.1 U31.H8(VCCINT_1) U31.H10(VCCINT_2) U31.J7(VCCINT_3) U31.J9(VCCINT_4)
VSS_SENSE: PR136.1 PR153.2 U1.AT75(VSS_VCCIN_SENSE)
10GBE_SPI_CLK_1V05: U1.M67(LAN_FLSH_CLK) U4.12(1B2)
10GBE_SPI_CLK_3V3: R20.1 U3.6(CLK)
10GBE_SPI_CLK_3V3_ST: R20.2 U4.5(1A2)
10GBE_SPI_CS_1V05_L: R11.1 U1.P67(L\A\N\_\F\L\S\H\_\C\S\) U4.11(2B1)
10GBE_SPI_CS_3V3_L: R4.1 R21.1 U3.1(C\S\)
10GBE_SPI_CS_3V3_ST_L: R21.2 U4.6(2A1)
10GBE_SPI_DI_1V05: U1.C73(LAN_FLSH_DI) U4.13(1B1)
10GBE_SPI_DO_1V05: R12.2 R16.2 U1.D74(LAN_FLSH_DO)
10GBE_SPI_DO_1V05_ST: R12.1 U2.4(B)
10GBE_SPI_HOLD_3V3_L: R5.1 U3.7(H\O\L\D\)
10GBE_SPI_MISO_3V3: R13.1 U2.3(A)
10GBE_SPI_MISO_3V3_ST: R13.2 U3.2(DO)
10GBE_SPI_MOSI_3V3: R19.1 U3.5(DIO)
10GBE_SPI_MOSI_3V3_ST: R19.2 U4.4(1A1)
10GBE_SPI_WP_3V3_L: R6.1 U3.3(W\P\)
ADC_CPU_TEMP_SENSOR: J10.B82(RSVD_5) U36.3(VOUT)
ADR_TRIGGER_L_GPIO37: R249.2 R254.1 U1.BL2(SATA3GP_GPIO37)
AUD_AZA_SDO: R299.2 R303.1 U1.BD22(MFG_MODE_STRAP)
BDX_CLKIN_SATA_N: R37.2 U1.BH33(CLKIN_GND4_DP)
BDX_CLKIN_SATA_P: R38.2 U1.BG32(CLKIN_GND4_DN)
BDXDE_CATERR_L: R193.2 U1.Y67(C\A\T\E\R\R\) U10.10(2B2)
BDXDE_CPU2PCH_THROT_1V05: R205.1 R252.2 R257.1 U1.AL74(THROTTLE_PECI_ID2)
BDXDE_CPU2PCH_THROT_1V05_R: R205.2 U15.4(1A1)
BDXDE_CPU2PCH_THROT_3V3: R204.2 R206.1 U15.13(1B1)
BDXDE_CPU_RSMRST_L: R104.2 R115.2 U1.R77(R\S\M\R\S\T\_\C\P\U\)
BDXDE_CPU_RSMRST_L_R: R104.1 U18.4(Y)
BDXDE_CPU_THERMTRIP_L: R197.2 U1.AF72(T\H\E\R\M\T\R\I\P\) U11.12(1B2)
BDXDE_DDR4_RESET_L: CN1.108(RESET_L) CN2.108(RESET_L) U1.CR43(D\D\R\_\R\E\S\E\T\)
BDXDE_DRAM01_PWROK: R69.2 U1.BA9(DRAMPWROK_PCH) U1.CV55(DRAM_PWR_OK)
BDXDE_ERR0_GTL_L: R196.2 U1.AC77(E\R\R\O\R\0\) U10.13(1B1)
BDXDE_ERR0_LVT3_L: R345.1 U10.4(1A1)
BDXDE_ERR0_LVT3_L_R: R345.2 U31.A9(FM_BDXDE_ERR0_LVT3_N)
BDXDE_ERR1_GTL_L: R195.2 U1.AC75(E\R\R\O\R\1\) U10.12(1B2)
BDXDE_ERR1_LVT3_L: R346.1 U10.5(1A2)
BDXDE_ERR1_LVT3_L_R: R346.2 U31.A8(FM_BDXDE_ERR1_LVT3_N)
BDXDE_ERR2_GTL_L: R194.2 U1.AB76(E\R\R\O\R\2\) U10.11(2B1)
BDXDE_ERR2_LVT3_L: U10.6(2A1) U31.A10(FM_BDXDE_ERR2_LVT3_N)
BDXDE_ME_DRIVE_L: R68.2 U1.BB23(GPIO28_MGPIO7) U31.B13(FM_BDXDE_ME_DRIVE_N)
BDXDE_PECID0: R258.2 R263.1 U1.L72(PECI_ID0)
BDXDE_PIRQC_L: R46.2 U35.7(B1)
BDXDE_PIRQD_L: R45.2 U35.6(B2)
BDXDE_PME_L: R79.2 U1.BE16(P\M\E\)
BDXDE_RESET_L: R123.2 R406.2 U1.BU7(P\L\T\R\S\T\_\P\R\O\C\) U1.L76(R\E\S\E\T\_\C\P\U\) U13.11(2B1)
BDXDE_RESET_L_R: J12.46 R406.1
BDXDE_RTCX1: C27.1 R61.2 U1.AT2(RTCX1) Y2.1
BDXDE_RTCX2: C26.1 R61.1 U1.AT4(RTCX2) Y2.2
BDXDE_SPKR: R298.2 R302.1 U1.BP20(SPKR)
BDXDE_SVID_ALERT_L: R108.1 U1.AK72(S\V\I\D\A\L\E\R\T\)
BDXDE_SVID_CLK: R107.1 U1.AH72(SVIDCLK)
BDXDE_SVID_DATA: R106.1 U1.AJ71(SVIDDATA)
BDXDE_SYS_RESET: Q2.1(B) Q3.3(C) R340.2
BDXDE_SYS_RESET_L: Q2.3(C) R338.2 U1.BL4(S\Y\S\_\R\E\S\E\T\)
BDXDE_THERMTRIP_L: J10.B50(PCIE0_TX8_P) R219.2
BDXDE_THERMTRIP_PCH_L: R213.2 U1.BJ16(T\H\E\R\M\T\R\I\P\_\P\C\H\) U19.4(Y)
BIOS_ADV_FUNCTIONS_GPIO36: R248.2 R253.2 U1.BT1(SATA2GP_GPIO36)
BIOS_CS_SEL_L: R223.1 U31.K1(BIOS_MUX_SEL)
BIOS_RCVR_BOOT_L: R289.2 R294.1 U1.BU22(GPIO55)
BMC_RTCRST_L: J10.B14(PCIE0_TX0_P) R312.1 R314.2
BMC_TO_HOST_INT_L: J10.B20(PCIE0_TX1_N) R357.2 R438.2
BMC_TO_HOST_INT_L_R: R357.1 U31.L1(BMC_TO_HOST_INT_L)
BMC_TO_HOST_NMI_L: J10.B19(PCIE0_TX1_P) R358.2 R437.2
BMC_TO_HOST_NMI_L_R: R358.1 U31.M1(BMC_TO_HOST_NMI_L)
BUILD_ID0: R423.1 R424.1 U31.E4(GND_17)
BUILD_ID1: R425.1 R426.1 U31.E5(GND_18)
CLK_25M_CPLD: R363.2 U31.J12(CLK_25M_CPLD)
CLK_25M_CPLD_ST: R363.1 Y4.3(OUT)
CLK_33M_BUF: R139.2 U9.1(BUF_IN)
CLK_33M_BUF_ST: R139.1 U1.AA9(CLKOUT_PCI0)
CLK_33M_LPC: R146.2 R149.1 U1.AC67(SERIRQ_CLK)
CLK_33M_LPC_EDGE: J10.B66(PCIE0_TX12_P) R151.2
CLK_33M_LPC_EDGE_ST: R151.1 U9.5(OUTPUT2)
CLK_33M_LPC_HDR: J1.1 R136.2
CLK_33M_LPC_HDR_ST: R136.1 U1.Y11(CLKOUT_PCI4)
CLK_33M_LPC_SL: R152.2 U31.J5(CLK_33M_LPC_CPLD)
CLK_33M_LPC_SL_ST: R152.1 U9.7(OUTPUT3)
CLK_33M_LPC_ST: R146.1 U9.3(OUTPUT1)
CLK_33M_PCICLKIN: R153.2 U1.AC7(CLKIN_PCILOOPBACK)
CLK_33M_PCICLKIN_BUF_ST: R153.1 U9.8(OUTPUT4)
CLK_100M_PCIE0_SLOT_N: J10.A14(PCIE0_REFCLK_N) U1.W2(CLKOUT_PEG_DN)
CLK_100M_PCIE0_SLOT_P: J10.A13(PCIE0_REFCLK_P) U1.W4(CLKOUT_PEG_DP)
CLK_100M_XDP_PE_N: J12.42 U1.H2(CLKOUT_ITPXDP_DN)
CLK_100M_XDP_PE_P: J12.40 U1.H4(CLKOUT_ITPXDP_DP)
CLK_DDR4_A_CK0_N: CN1.139(CLK0_N) U1.CJ47(DDR0_CLK_DN0)
CLK_DDR4_A_CK0_P: CN1.137(CLK0_P) U1.CL47(DDR0_CLK_DP0)
CLK_DDR4_A_CK2_N: CN1.140(CLK1_N) U1.CG47(DDR0_CLK_DN2)
CLK_DDR4_A_CK2_P: CN1.138(CLK1_P) U1.CF45(DDR0_CLK_DP2)
CLK_DDR4_B_CK0_N: CN2.139(CLK0_N) U1.CT58(DDR1_CLK_DN0)
CLK_DDR4_B_CK0_P: CN2.137(CLK0_P) U1.CV58(DDR1_CLK_DP0)
CLK_DDR4_B_CK2_N: CN2.140(CLK1_N) U1.CR57(DDR1_CLK_DN2)
CLK_DDR4_B_CK2_P: CN2.138(CLK1_P) U1.CU57(DDR1_CLK_DP2)
CLK_M2_SUSCLK: J9.68(SUSCLK) R52.2 U31.H5(CLK_M2_SUSCLK_CPLD)
CLK_M2_SUSCLK_ST: R52.1 R250.2 R255.1 U1.BD11(SUSCLK_GPIO62)
CLK_SVID_CPU: PR108.1 PR111.1 PR171.1 PR174.1 PR180.1 PR197.1 R107.2 R465.2
CLK_XDP_CPU_TCK: R179.1 R411.1 R464.2 U1.T76(JTAG_TCK_CPU)
CMOS_CLR: Q6.1(B) R460.2 U31.C13(GND_6)
CORE_VRHOT_L: PR209.2 PU17.30(VR_HOT#) U33.1(B)
CPLD_BDXDE_THERMTRIP_L: R219.1 U11.5(1A2) U31.A5(CPLD_BDXDE_THERMTRIP_N)
CPLD_CATERR_L_LATCH: U30.6(I/O_0.2) U31.D1(CPLD_CATERR_N_LATCH)
CPLD_CLEAR_LATCH: U30.13(I/O_1.0) U31.F1(CPLD_CLEAR_LATCH)
CPLD_CPU2PCH_THROT: R206.2 U31.N15(THROTTLE_PECI_ID2)
CPLD_CPU_DIMM_EVENT_CO_L: U31.B4(CPLD_CPU_DIMM_EVENT_CO_N) U32.4(B)
CPLD_DEBUG_MODE: R360.2 R362.1 U31.T2(FM_CPLD_DEBUG_MODE)
CPLD_ERROR0_L_LATCH: U30.7(I/O_0.3) U31.D3(CPLD_ERROR0_LATCH)
CPLD_ERROR1_L_LATCH: U30.8(I/O_0.4) U31.E2(CPLD_ERROR1_LATCH)
CPLD_ERROR2_L_LATCH: U30.9(I/O_0.5) U31.E3(CPLD_ERROR2_LATCH)
CPLD_FAST_PROCHOT_L: R220.1 R347.1 U14.12(1B2)
CPLD_FAST_PROCHOT_L_R: R347.2 U31.C4(CPLD_FAST_PROCHOT_N_R)
CPLD_FIVR_FAULT: U13.7(2A2) U31.B8(CPLD_FIVR_FAULT)
CPLD_GPIO27_MGPIO6: R89.2 U1.BB16(GPIO27_MGPIO6) U31.B6(CPLD_GPIO27_MGPIO6)
CPLD_M2_DEVSLP: R390.1 U31.E16(CPLD_M2_DEVSLP)
CPLD_M2_DEVSLP_R: J9.38(DEVSLP) R390.2
CPLD_PCH_THERMTRIP_L: U19.2(A) U31.A7(CPLD_PCH_THERMTRIP_N)
CPLD_PCHHOT_L_LATCH: U30.5(I/O_0.1) U31.D2(CPLD_PCHHOT_N_GP74_LATCH)
CPLD_PCIE_RESET_L: J10.B30(RSVD_7) R344.1
CPLD_PCIE_RESET_L_R: R344.2 U31.R3(CPLD_PCIE_RESET_N)
CPLD_PIRQC_L: U31.K15(PIRQC_N) U35.2(A1)
CPLD_PIRQD_L: U31.L15(PIRQD_N) U35.3(A2)
CPLD_PIRQE_L_GPIO2: R44.2 U31.K16(PIRQE_N_GPIO2)
CPLD_PIRQE_L_GPIO2_R: R44.1 R442.2 U1.BV16(PIRQE_N_GPIO2)
CPLD_PIRQF_L_GPIO3: R43.2 U31.L16(PIRQF_N_GPIO3)
CPLD_PIRQF_L_GPIO3_R: R43.1 R441.2 U1.BN22(PIRQF_N_GPIO3)
CPLD_PIRQG_L_GPIO4: R42.2 U31.M16(PIRQG_N_GPIO4)
CPLD_PIRQG_L_GPIO4_R: R42.1 R440.2 U1.BL22(PIRQG_N_GPIO4)
CPLD_PIRQH_L_GPIO5: R41.2 U31.M15(PIRQH_N_GPIO5)
CPLD_PIRQH_L_GPIO5_R: R41.1 R439.2 U1.BW22(PIRQH_N_GPIO5)
CPLD_PLTRST_L_LATCH: U30.15(I/O_1.2) U31.E1(CPLD_PLTRST_LATCH)
CPLD_PROCHOT_L_LATCH: U30.4(I/O_0.0) U31.F2(CPLD_PROCHOT_LATCH)
CPLD_RTCRST_L: R314.1 U31.J13(GND_52)
CPLD_THERMTRIP_L_LATCH: U30.20(I/O_1.7) U31.F3(CPLD_THERMTRIP_N_LATCH)
CPLD_VRHOT_L: U31.D16(CPLD_VR_HOT_N) U33.4(Y)
CPU_BOOT_DONE: J10.B78(PCIE0_TX15_P) U1.BW18(GPIO54)
CPU_DCPRTC: C38.1 U1.AW16(DCPRTC)
CPU_DCPSST: C183.1 U1.AW19(DCPSST)
CPU_DCPSUS1: C180.1 U1.AU16(DCPSUS1)
CPU_DCPSUS2: C176.1 U1.AK14(DCPSUS2)
CPU_DCPSUS3: C181.1 U1.AP28(DCPSUS31) U1.AP30(DCPSUS30)
CPU_DCPSUSBY: C179.1 U1.AU21(DCPSUSBYP1) U1.AW21(DCPSUSBYP0)
CPU_DIMM_EVENT_CO_L: CN1.134(EVENT_L) CN2.134(EVENT_L) R359.1 U32.3(A)
CPU_GPIO44_R: R49.1 U1.BD18(GPIO44)
CPU_GPIO45_R: R48.1 U1.BA21(GPIO45)
CPU_GPIO46_R: R47.1 U1.BA19(GPIO46)
CPU_I2C1_ALERT_L_1V05: R199.2 U1.AN71(L\A\N\_\S\M\B\A\L\R\T\)
CPU_I2C1_ALERT_L_1V05_R: R198.2 R199.1 U11.11(2B1)
CPU_I2C1_ALERT_L_3V3: J10.A50(RSVD_4) U11.6(2A1)
CPU_PECI: R105.1 R124.2 U1.AL78(PECI_CPU)
CPU_PROCHOT_L: U1.AV7(TACH4_GPIO68)
CPU_PRSNT_L: J10.A1(PRSNT1_L) J10.B81(PRSNT2_4_L)
CPU_PWR_DEBUG_L: C192.1 J12.45 R401.2 U1.U77(P\W\R\_\D\E\B\U\G\)
CPU_RSVD95: R168.1 U1.A76(RSVD95)
CPU_THERMTRIP_L: U1.AU9(TACH5_GPIO69)
CPU_THROTTLE_L: R177.2 U1.BN2(SATA4GP_GPIO16) U17.2(A)
CPU_THROTTLE_L_R: R211.2 U31.A4(FM_CPU_THROTTLE_N_R)
CPU_THROTTLE_R1_L: R210.2 R211.1 U17.4(Y)
CPU_UART0_RXD_1V05: R112.2 R456.1 U1.AG77(UART_RXD0)
CPU_UART0_RXD_3V3: J2.3 J10.A56(PCIE0_RX9_P) U8.7(2A2)
CPU_UART0_TXD_1V05: R268.2 R274.1 R454.1 U1.AG75(UART_TXD0)
CPU_UART0_TXD_3V3: J2.2 J10.A57(PCIE0_RX9_N) R458.2
CPU_UART1_RXD_1V05: R111.2 R455.1 U1.AH78(UART_RXD1)
CPU_UART1_RXD_3V3: J10.B55(PCIE0_TX9_N) U8.6(2A1)
CPU_UART1_TXD_1V05: R269.2 R275.1 R453.1 U1.AH76(UART_TXD1)
CPU_UART1_TXD_3V3: J10.B54(PCIE0_TX9_P) R457.2
CPU_VCC_SENSE: C182.1 U1.BT5(VCC_SENSE)
DDR4_A_A0: CN1.144(A0) U1.CK49(DDR0_MA_0)
DDR4_A_A1: CN1.133(A1) U1.CK41(DDR0_MA_1)
DDR4_A_A2: CN1.132(A2) U1.CM41(DDR0_MA_2)
DDR4_A_A3: CN1.131(A3) U1.CF41(DDR0_MA_3)
DDR4_A_A4: CN1.128(A4) U1.CL39(DDR0_MA_4)
DDR4_A_A5: CN1.126(A5) U1.CG39(DDR0_MA_5)
DDR4_A_A6: CN1.127(A6) U1.CK37(DDR0_MA_6)
DDR4_A_A7: CN1.122(A7) U1.CD39(DDR0_MA_7)
DDR4_A_A8: CN1.125(A8) U1.CM37(DDR0_MA_8)
DDR4_A_A9: CN1.121(A9) U1.CJ35(DDR0_MA_9)
DDR4_A_A10: CN1.146(A10_AP) U1.CJ51(DDR0_MA_10)
DDR4_A_A11: CN1.120(A11) U1.CG35(DDR0_MA_11)
DDR4_A_A12: CN1.119(A12) U1.CF37(DDR0_MA_12)
DDR4_A_A13: CN1.158(A13) U1.CK56(DDR0_MA_13)
DDR4_A_A14: CN1.151(A14_WE_L) U1.CM52(D\D\R\0\_\M\A\1\4\_\W\E\)
DDR4_A_A15: CN1.156(A15_CAS_L) U1.CJ54(D\D\R\0\_\M\A\1\5\_\C\A\S\)
DDR4_A_A16: CN1.152(A16_RAS_L) U1.CF49(D\D\R\0\_\M\A\1\6\_\R\A\S\)
DDR4_A_ACT_L: CN1.114(ACT_L) U1.CF33(DDR0_ACT_N_MA15)
DDR4_A_ALERT_L: CN1.116(ALERT_L) U1.CK33(D\D\R\0\_\A\L\E\R\T\_\N\_\P\A\R)
DDR4_A_BA0: CN1.150(BA0) U1.CH52(DDR0_BA0)
DDR4_A_BA1: CN1.145(BA1) U1.CL51(DDR0_BA1)
DDR4_A_BG0: CN1.115(BG0) U1.CM33(DDR0_BG0_BA2)
DDR4_A_BG1: CN1.113(BG1) U1.CD35(DDR0_BG1_MA14)
DDR4_A_CKE0: CN1.109(CKE0) U1.CD32(DDR0_CKE0)
DDR4_A_CKE1: CN1.110(CKE1) U1.CG32(DDR0_CKE1)
DDR4_A_CS0_L: CN1.149(CS0_L) U1.CL54(D\D\R\0\_\C\S\0\)
DDR4_A_CS1_L: CN1.157(CS1_L) U1.CJ58(D\D\R\0\_\C\S\1\)
DDR4_A_DQ0: CN1.8(DQ0) U1.BY2(DDR0_DQ0)
DDR4_A_DQ1: CN1.7(DQ1) U1.BY4(DDR0_DQ1)
DDR4_A_DQ2: CN1.20(DQ2) U1.CD2(DDR0_DQ2)
DDR4_A_DQ3: CN1.21(DQ3) U1.CD4(DDR0_DQ3)
DDR4_A_DQ4: CN1.4(DQ4) U1.BW1(DDR0_DQ4)
DDR4_A_DQ5: CN1.3(DQ5) U1.BW3(DDR0_DQ5)
DDR4_A_DQ6: CN1.16(DQ6) U1.CC1(DDR0_DQ6)
DDR4_A_DQ7: CN1.17(DQ7) U1.CC3(DDR0_DQ7)
DDR4_A_DQ8: CN1.28(DQ8) U1.CC7(DDR0_DQ8)
DDR4_A_DQ9: CN1.29(DQ9) U1.CB9(DDR0_DQ9)
DDR4_A_DQ10: CN1.41(DQ10) U1.CM7(DDR0_DQ10)
DDR4_A_DQ11: CN1.42(DQ11) U1.CL9(DDR0_DQ11)
DDR4_A_DQ12: CN1.24(DQ12) U1.CA7(DDR0_DQ12)
DDR4_A_DQ13: CN1.25(DQ13) U1.BY9(DDR0_DQ13)
DDR4_A_DQ14: CN1.38(DQ14) U1.CK7(DDR0_DQ14)
DDR4_A_DQ15: CN1.37(DQ15) U1.CJ9(DDR0_DQ15)
DDR4_A_DQ16: CN1.50(DQ16) U1.CB13(DDR0_DQ16)
DDR4_A_DQ17: CN1.49(DQ17) U1.CC14(DDR0_DQ17)
DDR4_A_DQ18: CN1.62(DQ18) U1.CL13(DDR0_DQ18)
DDR4_A_DQ19: CN1.63(DQ19) U1.CM14(DDR0_DQ19)
DDR4_A_DQ20: CN1.46(DQ20) U1.BY13(DDR0_DQ20)
DDR4_A_DQ21: CN1.45(DQ21) U1.CA14(DDR0_DQ21)
DDR4_A_DQ22: CN1.58(DQ22) U1.CJ13(DDR0_DQ22)
DDR4_A_DQ23: CN1.59(DQ23) U1.CK14(DDR0_DQ23)
DDR4_A_DQ24: CN1.70(DQ24) U1.CD20(DDR0_DQ24)
DDR4_A_DQ25: CN1.71(DQ25) U1.CB20(DDR0_DQ25)
DDR4_A_DQ26: CN1.83(DQ26) U1.CD28(DDR0_DQ26)
DDR4_A_DQ27: CN1.84(DQ27) U1.CB28(DDR0_DQ27)
DDR4_A_DQ28: CN1.66(DQ28) U1.CF18(DDR0_DQ28)
DDR4_A_DQ29: CN1.67(DQ29) U1.CC18(DDR0_DQ29)
DDR4_A_DQ30: CN1.79(DQ30) U1.CF26(DDR0_DQ30)
DDR4_A_DQ31: CN1.80(DQ31) U1.CC26(DDR0_DQ31)
DDR4_A_DQ32: CN1.174(DQ32) U1.CD66(DDR0_DQ32)
DDR4_A_DQ33: CN1.173(DQ33) U1.CB66(DDR0_DQ33)
DDR4_A_DQ34: CN1.187(DQ34) U1.CD72(DDR0_DQ34)
DDR4_A_DQ35: CN1.186(DQ35) U1.CB72(DDR0_DQ35)
DDR4_A_DQ36: CN1.170(DQ36) U1.CF64(DDR0_DQ36)
DDR4_A_DQ37: CN1.169(DQ37) U1.CC64(DDR0_DQ37)
DDR4_A_DQ38: CN1.183(DQ38) U1.CF71(DDR0_DQ38)
DDR4_A_DQ39: CN1.182(DQ39) U1.CC71(DDR0_DQ39)
DDR4_A_DQ40: CN1.195(DQ40) U1.CL66(DDR0_DQ40)
DDR4_A_DQ41: CN1.194(DQ41) U1.CJ66(DDR0_DQ41)
DDR4_A_DQ42: CN1.207(DQ42) U1.CL72(DDR0_DQ42)
DDR4_A_DQ43: CN1.208(DQ43) U1.CJ72(DDR0_DQ43)
DDR4_A_DQ44: CN1.191(DQ44) U1.CM64(DDR0_DQ44)
DDR4_A_DQ45: CN1.190(DQ45) U1.CK64(DDR0_DQ45)
DDR4_A_DQ46: CN1.203(DQ46) U1.CM71(DDR0_DQ46)
DDR4_A_DQ47: CN1.204(DQ47) U1.CK71(DDR0_DQ47)
DDR4_A_DQ48: CN1.216(DQ48) U1.BT72(DDR0_DQ48)
DDR4_A_DQ49: CN1.215(DQ49) U1.BU71(DDR0_DQ49)
DDR4_A_DQ50: CN1.228(DQ50) U1.BG72(DDR0_DQ50)
DDR4_A_DQ51: CN1.229(DQ51) U1.BH71(DDR0_DQ51)
DDR4_A_DQ52: CN1.211(DQ52) U1.BV72(DDR0_DQ52)
DDR4_A_DQ53: CN1.212(DQ53) U1.BW71(DDR0_DQ53)
DDR4_A_DQ54: CN1.224(DQ54) U1.BJ72(DDR0_DQ54)
DDR4_A_DQ55: CN1.225(DQ55) U1.BL71(DDR0_DQ55)
DDR4_A_DQ56: CN1.237(DQ56) U1.BU67(DDR0_DQ56)
DDR4_A_DQ57: CN1.236(DQ57) U1.BT66(DDR0_DQ57)
DDR4_A_DQ58: CN1.249(DQ58) U1.BH67(DDR0_DQ58)
DDR4_A_DQ59: CN1.250(DQ59) U1.BG66(DDR0_DQ59)
DDR4_A_DQ60: CN1.232(DQ60) U1.BW67(DDR0_DQ60)
DDR4_A_DQ61: CN1.233(DQ61) U1.BV66(DDR0_DQ61)
DDR4_A_DQ62: CN1.245(DQ62) U1.BL67(DDR0_DQ62)
DDR4_A_DQ63: CN1.246(DQ63) U1.BJ66(DDR0_DQ63)
DDR4_A_DQS0_N: CN1.11(DQS0_N) U1.CB4(DDR0_DQS_DN0)
DDR4_A_DQS0_P: CN1.13(DQS0_P) U1.CB2(DDR0_DQS_DP0)
DDR4_A_DQS1_N: CN1.32(DQS1_N) U1.CH7(DDR0_DQS_DN1)
DDR4_A_DQS1_P: CN1.34(DQS1_P) U1.CG9(DDR0_DQS_DP1)
DDR4_A_DQS2_N: CN1.53(DQS2_N) U1.CG13(DDR0_DQS_DN2)
DDR4_A_DQS2_P: CN1.55(DQS2_P) U1.CH14(DDR0_DQS_DP2)
DDR4_A_DQS3_N: CN1.74(DQS3_N) U1.CD24(DDR0_DQS_DN3)
DDR4_A_DQS3_P: CN1.76(DQS3_P) U1.CB24(DDR0_DQS_DP3)
DDR4_A_DQS4_N: CN1.177(DQS4_N) U1.CD69(DDR0_DQS_DN4)
DDR4_A_DQS4_P: CN1.179(DQS4_P) U1.CB69(DDR0_DQS_DP4)
DDR4_A_DQS5_N: CN1.198(DQS5_N) U1.CL69(DDR0_DQS_DN5)
DDR4_A_DQS5_P: CN1.200(DQS5_P) U1.CJ69(DDR0_DQS_DP5)
DDR4_A_DQS6_N: CN1.219(DQS6_N) U1.BM72(DDR0_DQS_DN6)
DDR4_A_DQS6_P: CN1.221(DQS6_P) U1.BN71(DDR0_DQS_DP6)
DDR4_A_DQS7_N: CN1.240(DQS7_N) U1.BN67(DDR0_DQS_DN7)
DDR4_A_DQS7_P: CN1.242(DQS7_P) U1.BM66(DDR0_DQS_DP7)
DDR4_A_DQS8_N: CN1.95(DQS8_N) U1.CL24(DDR0_DQS_DN8)
DDR4_A_DQS8_P: CN1.97(DQS8_P) U1.CJ24(DDR0_DQS_DP8)
DDR4_A_ECC0: CN1.92(CB0_NC) U1.CL20(DDR0_ECC0)
DDR4_A_ECC1: CN1.91(CB1_NC) U1.CJ20(DDR0_ECC1)
DDR4_A_ECC2: CN1.101(CB2_NC) U1.CL28(DDR0_ECC2)
DDR4_A_ECC3: CN1.105(CB3_NC) U1.CJ28(DDR0_ECC3)
DDR4_A_ECC4: CN1.88(CB4_NC) U1.CM18(DDR0_ECC4)
DDR4_A_ECC5: CN1.87(CB5_NC) U1.CK18(DDR0_ECC5)
DDR4_A_ECC6: CN1.100(CB6_NC) U1.CM26(DDR0_ECC6)
DDR4_A_ECC7: CN1.104(CB7_NC) U1.CK26(DDR0_ECC7)
DDR4_A_ODT0: CN1.155(ODT0) U1.CF56(DDR0_ODT0)
DDR4_A_ODT1: CN1.161(ODT1) U1.CM60(DDR0_ODT1)
DDR4_A_PAR: CN1.143(PARITY) U1.CM49(DDR0_PAR)
DDR4_A_SA0: CN1.256(SA0) R229.2 R232.1
DDR4_A_SA1: CN1.260(SA1) R230.2 R233.1
DDR4_A_SA2: CN1.166(SA2) R231.2 R234.1
DDR4_B_A0: CN2.144(A0) U1.CV60(DDR1_MA_0)
DDR4_B_A1: CN2.133(A1) U1.CU50(DDR1_MA_1)
DDR4_B_A2: CN2.132(A2) U1.CR50(DDR1_MA_2)
DDR4_B_A3: CN2.131(A3) U1.CT49(DDR1_MA_3)
DDR4_B_A4: CN2.128(A4) U1.CV49(DDR1_MA_4)
DDR4_B_A5: CN2.126(A5) U1.CR48(DDR1_MA_5)
DDR4_B_A6: CN2.127(A6) U1.CT47(DDR1_MA_6)
DDR4_B_A7: CN2.122(A7) U1.CR46(DDR1_MA_7)
DDR4_B_A8: CN2.125(A8) U1.CV47(DDR1_MA_8)
DDR4_B_A9: CN2.121(A9) U1.CT44(DDR1_MA_9)
DDR4_B_A10: CN2.146(A10_AP) U1.CU61(DDR1_MA_10)
DDR4_B_A11: CN2.120(A11) U1.CU46(DDR1_MA_11)
DDR4_B_A12: CN2.119(A12) U1.CV44(DDR1_MA_12)
DDR4_B_A13: CN2.158(A13) U1.CT66(DDR1_MA_13)
DDR4_B_A14: CN2.151(A14_WE_L) U1.CV62(D\D\R\1\_\M\A\1\4\_\W\E\)
DDR4_B_A15: CN2.156(A15_CAS_L) U1.CT64(D\D\R\1\_\M\A\1\5\_\C\A\S\)
DDR4_B_A16: CN2.152(A16_RAS_L) U1.CT62(D\D\R\1\_\M\A\1\6\_\R\A\S\)
DDR4_B_ACT_L: CN2.114(ACT_L) U1.CU41(DDR1_ACT_N_MA_15)
DDR4_B_ALERT_L: CN2.116(ALERT_L) U1.CT42(D\D\R\1\_\A\L\E\R\T\_\N\_\P\A\R)
DDR4_B_BA0: CN2.150(BA0) U1.CR61(DDR1_BA0)
DDR4_B_BA1: CN2.145(BA1) U1.CT60(DDR1_BA1)
DDR4_B_BG0: CN2.115(BG0) U1.CR41(DDR1_BG0_BA_2)
DDR4_B_BG1: CN2.113(BG1) U1.CV42(DDR1_BG1_MA_14)
DDR4_B_CKE0: CN2.109(CKE0) U1.CT40(DDR1_CKE0)
DDR4_B_CKE1: CN2.110(CKE1) U1.CV38(DDR1_CKE1)
DDR4_B_CS0_L: CN2.149(CS0_L) U1.CR63(D\D\R\1\_\C\S\0)
DDR4_B_CS1_L: CN2.157(CS1_L) U1.CV66(D\D\R\1\_\C\S\1\)
DDR4_B_DQ0: CN2.8(DQ0) U1.CG1(DDR1_DQ0)
DDR4_B_DQ1: CN2.7(DQ1) U1.CG3(DDR1_DQ1)
DDR4_B_DQ2: CN2.20(DQ2) U1.CM3(DDR1_DQ2)
DDR4_B_DQ3: CN2.21(DQ3) U1.CN4(DDR1_DQ3)
DDR4_B_DQ4: CN2.4(DQ4) U1.CF2(DDR1_DQ4)
DDR4_B_DQ5: CN2.3(DQ5) U1.CF4(DDR1_DQ5)
DDR4_B_DQ6: CN2.16(DQ6) U1.CL2(DDR1_DQ6)
DDR4_B_DQ7: CN2.17(DQ7) U1.CK4(DDR1_DQ7)
DDR4_B_DQ8: CN2.28(DQ8) U1.CU8(DDR1_DQ8)
DDR4_B_DQ9: CN2.29(DQ9) U1.CR8(DDR1_DQ9)
DDR4_B_DQ10: CN2.41(DQ10) U1.CU13(DDR1_DQ10)
DDR4_B_DQ11: CN2.42(DQ11) U1.CR13(DDR1_DQ11)
DDR4_B_DQ12: CN2.24(DQ12) U1.CU5(DDR1_DQ12)
DDR4_B_DQ13: CN2.25(DQ13) U1.CT7(DDR1_DQ13)
DDR4_B_DQ14: CN2.38(DQ14) U1.CV12(DDR1_DQ14)
DDR4_B_DQ15: CN2.37(DQ15) U1.CT12(DDR1_DQ15)
DDR4_B_DQ16: CN2.50(DQ16) U1.CV16(DDR1_DQ16)
DDR4_B_DQ17: CN2.49(DQ17) U1.CT16(DDR1_DQ17)
DDR4_B_DQ18: CN2.62(DQ18) U1.CV20(DDR1_DQ18)
DDR4_B_DQ19: CN2.63(DQ19) U1.CT20(DDR1_DQ19)
DDR4_B_DQ20: CN2.46(DQ20) U1.CU15(DDR1_DQ20)
DDR4_B_DQ21: CN2.45(DQ21) U1.CR15(DDR1_DQ21)
DDR4_B_DQ22: CN2.58(DQ22) U1.CU19(DDR1_DQ22)
DDR4_B_DQ23: CN2.59(DQ23) U1.CR19(DDR1_DQ23)
DDR4_B_DQ24: CN2.70(DQ24) U1.CU24(DDR1_DQ24)
DDR4_B_DQ25: CN2.71(DQ25) U1.CR24(DDR1_DQ25)
DDR4_B_DQ26: CN2.83(DQ26) U1.CU28(DDR1_DQ26)
DDR4_B_DQ27: CN2.84(DQ27) U1.CR28(DDR1_DQ27)
DDR4_B_DQ28: CN2.66(DQ28) U1.CV23(DDR1_DQ28)
DDR4_B_DQ29: CN2.67(DQ29) U1.CT23(DDR1_DQ29)
DDR4_B_DQ30: CN2.79(DQ30) U1.CV27(DDR1_DQ30)
DDR4_B_DQ31: CN2.80(DQ31) U1.CT27(DDR1_DQ31)
DDR4_B_DQ32: CN2.174(DQ32) U1.CT73(DDR1_DQ32)
DDR4_B_DQ33: CN2.173(DQ33) U1.CU74(DDR1_DQ33)
DDR4_B_DQ34: CN2.187(DQ34) U1.CJ78(DDR1_DQ34)
DDR4_B_DQ35: CN2.186(DQ35) U1.CJ76(DDR1_DQ35)
DDR4_B_DQ36: CN2.170(DQ36) U1.CU71(DDR1_DQ36)
DDR4_B_DQ37: CN2.169(DQ37) U1.CR71(DDR1_DQ37)
DDR4_B_DQ38: CN2.183(DQ38) U1.CL77(DDR1_DQ38)
DDR4_B_DQ39: CN2.182(DQ39) U1.CK75(DDR1_DQ39)
DDR4_B_DQ40: CN2.195(DQ40) U1.CF77(DDR1_DQ40)
DDR4_B_DQ41: CN2.194(DQ41) U1.CF75(DDR1_DQ41)
DDR4_B_DQ42: CN2.207(DQ42) U1.CB77(DDR1_DQ42)
DDR4_B_DQ43: CN2.208(DQ43) U1.CB75(DDR1_DQ43)
DDR4_B_DQ44: CN2.191(DQ44) U1.CG78(DDR1_DQ44)
DDR4_B_DQ45: CN2.190(DQ45) U1.CG76(DDR1_DQ45)
DDR4_B_DQ46: CN2.203(DQ46) U1.CC78(DDR1_DQ46)
DDR4_B_DQ47: CN2.204(DQ47) U1.CC76(DDR1_DQ47)
DDR4_B_DQ48: CN2.216(DQ48) U1.BW78(DDR1_DQ48)
DDR4_B_DQ49: CN2.215(DQ49) U1.BW76(DDR1_DQ49)
DDR4_B_DQ50: CN2.228(DQ50) U1.BP78(DDR1_DQ50)
DDR4_B_DQ51: CN2.229(DQ51) U1.BP76(DDR1_DQ51)
DDR4_B_DQ52: CN2.211(DQ52) U1.BY77(DDR1_DQ52)
DDR4_B_DQ53: CN2.212(DQ53) U1.BY75(DDR1_DQ53)
DDR4_B_DQ54: CN2.224(DQ54) U1.BR77(DDR1_DQ54)
DDR4_B_DQ55: CN2.225(DQ55) U1.BR75(DDR1_DQ55)
DDR4_B_DQ56: CN2.237(DQ56) U1.BL77(DDR1_DQ56)
DDR4_B_DQ57: CN2.236(DQ57) U1.BL75(DDR1_DQ57)
DDR4_B_DQ58: CN2.249(DQ58) U1.BG77(DDR1_DQ58)
DDR4_B_DQ59: CN2.250(DQ59) U1.BG75(DDR1_DQ59)
DDR4_B_DQ60: CN2.232(DQ60) U1.BM78(DDR1_DQ60)
DDR4_B_DQ61: CN2.233(DQ61) U1.BM76(DDR1_DQ61)
DDR4_B_DQ62: CN2.245(DQ62) U1.BH78(DDR1_DQ62)
DDR4_B_DQ63: CN2.246(DQ63) U1.BH76(DDR1_DQ63)
DDR4_B_DQS0_N: CN2.11(DQS0_N) U1.CJ1(DDR1_DQS_DN0)
DDR4_B_DQS0_P: CN2.13(DQS0_P) U1.CJ3(DDR1_DQS_DP0)
DDR4_B_DQS1_N: CN2.32(DQS1_N) U1.CU10(DDR1_DQS_DN1)
DDR4_B_DQS1_P: CN2.34(DQS1_P) U1.CR10(DDR1_DQS_DP1)
DDR4_B_DQS2_N: CN2.53(DQS2_N) U1.CV18(DDR1_DQS_DN2)
DDR4_B_DQS2_P: CN2.55(DQS2_P) U1.CT18(DDR1_DQS_DP2)
DDR4_B_DQS3_N: CN2.74(DQS3_N) U1.CU26(DDR1_DQS_DN3)
DDR4_B_DQS3_P: CN2.76(DQS3_P) U1.CR26(DDR1_DQS_DP3)
DDR4_B_DQS4_N: CN2.177(DQS4_N) U1.CM76(DDR1_DQS_DN4)
DDR4_B_DQS4_P: CN2.179(DQS4_P) U1.CN75(DDR1_DQS_DP4)
DDR4_B_DQS5_N: CN2.198(DQS5_N) U1.CD77(DDR1_DQS_DN5)
DDR4_B_DQS5_P: CN2.200(DQS5_P) U1.CD75(DDR1_DQS_DP5)
DDR4_B_DQS6_N: CN2.219(DQS6_N) U1.BT78(DDR1_DQS_DN6)
DDR4_B_DQS6_P: CN2.221(DQS6_P) U1.BT76(DDR1_DQS_DP6)
DDR4_B_DQS7_N: CN2.240(DQS7_N) U1.BJ77(DDR1_DQS_DN7)
DDR4_B_DQS7_P: CN2.242(DQS7_P) U1.BJ75(DDR1_DQS_DP7)
DDR4_B_DQS8_N: CN2.95(DQS8_N) U1.CV34(DDR1_DQS_DN8)
DDR4_B_DQS8_P: CN2.97(DQS8_P) U1.CT34(DDR1_DQS_DP8)
DDR4_B_ECC0: CN2.92(CB0_NC) U1.CV31(DDR1_ECC0)
DDR4_B_ECC1: CN2.91(CB1_NC) U1.CT31(DDR1_ECC1)
DDR4_B_ECC2: CN2.101(CB2_NC) U1.CV36(DDR1_ECC2)
DDR4_B_ECC3: CN2.105(CB3_NC) U1.CT36(DDR1_ECC3)
DDR4_B_ECC4: CN2.88(CB4_NC) U1.CU30(DDR1_ECC4)
DDR4_B_ECC5: CN2.87(CB5_NC) U1.CR30(DDR1_ECC5)
DDR4_B_ECC6: CN2.100(CB6_NC) U1.CU35(DDR1_ECC6)
